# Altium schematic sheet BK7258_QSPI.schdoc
size 332 x 191 mm
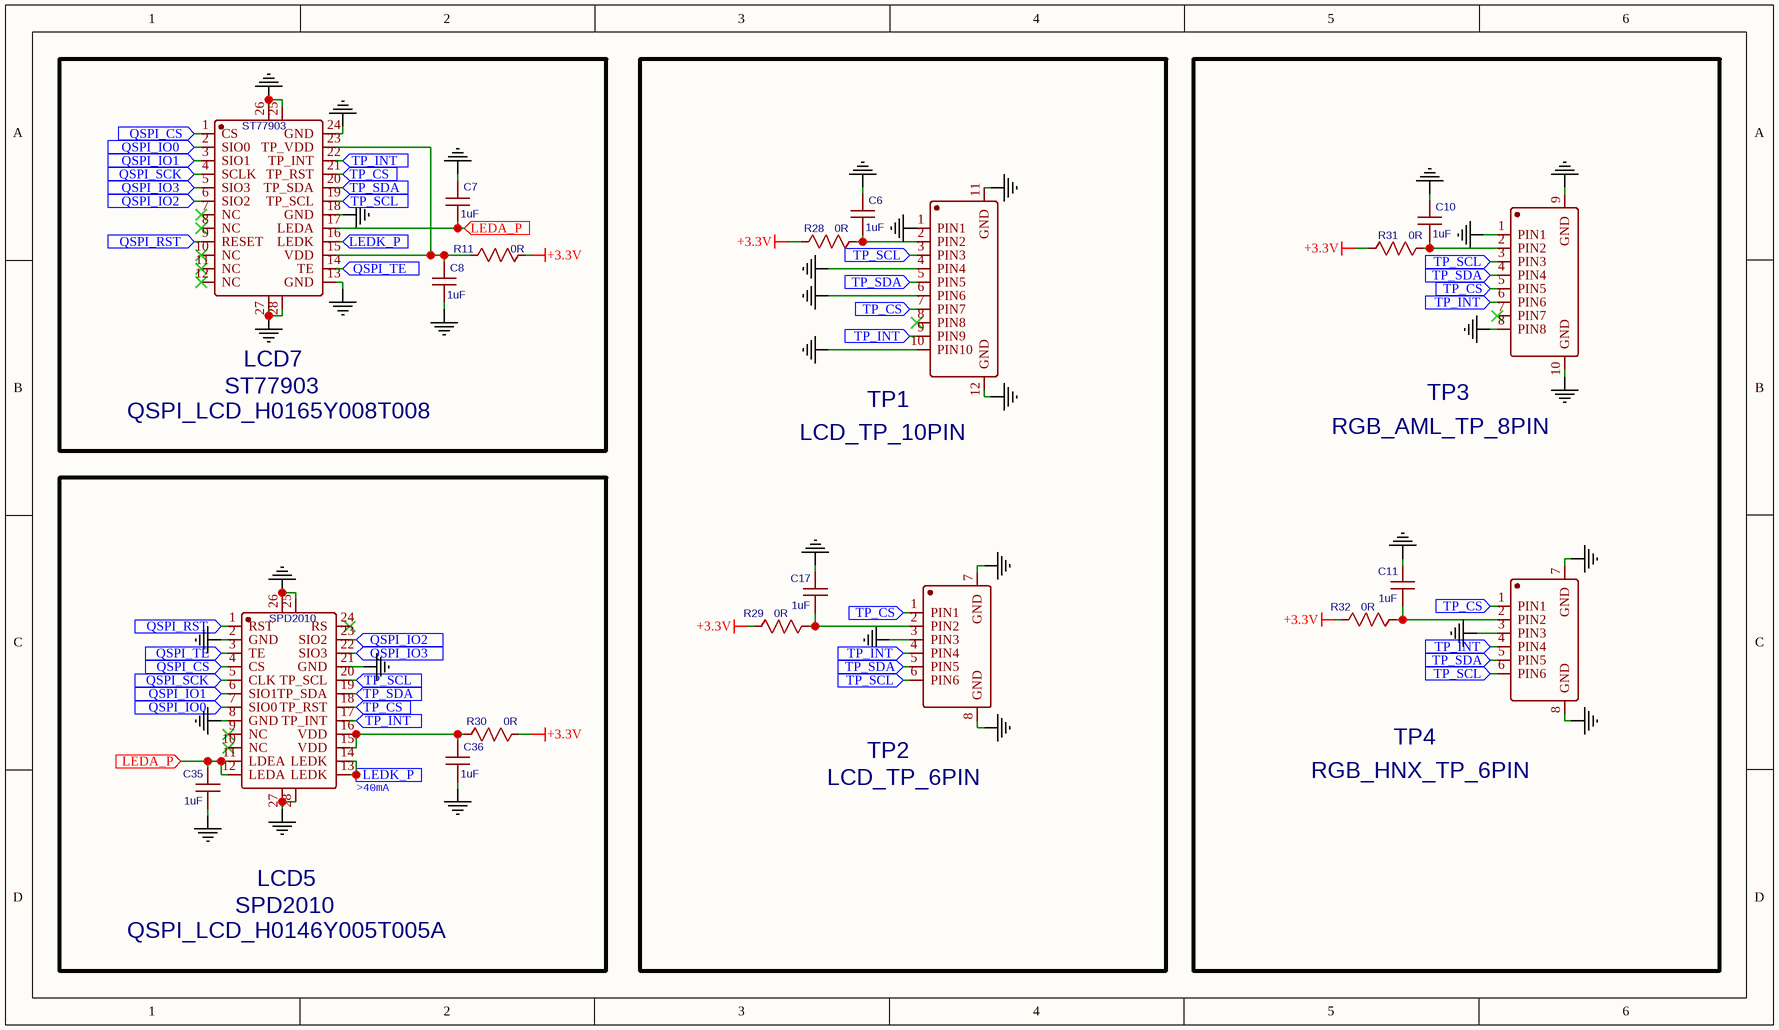
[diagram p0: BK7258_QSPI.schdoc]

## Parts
C6  1uF  [C0402]
C7  1uF  [C0402]
C8  1uF  [C0402]
C10  1uF  [C0402]
C11  1uF  [C0402]
C17  1uF  [C0402]
C35  1uF  [C0402]
C36  1uF  [C0402]
LCD5  SPD2010  [CONN-SMD_24P-P0.40_OK-14F024-04]
LCD7  ST77903  [CONN-SMD_24P-P0.40_OK-14F024-04]
R11  0R  [R0402]
R28  0R  [R0402]
R29  0R  [R0402]
R30  0R  [R0402]
R31  0R  [R0402]
R32  0R  [R0402]
TP1  LCD_TP_10PIN  [FPC-SMD_P0.5-10P_FGS-XJ-H2.0]
TP2  LCD_TP_6PIN  [CON6-FPC-AAAAA]
TP3  RGB_AML_TP_8PIN  [FPC-SMD_P0.50-8P_FGS-XJ-H2.0]
TP4  RGB_HNX_TP_6PIN  [CON6-FPC-HNX]

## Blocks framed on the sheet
QSPI_LCD_H0165Y008T008: C7 C8 LCD7 R11
QSPI_LCD_H0146Y005T005A: C35 C36 LCD5 R30

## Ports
LEDA_P (in), LEDK_P (in), QSPI_CS (in), QSPI_IO0 (in), QSPI_IO1 (in), QSPI_IO2 (in), QSPI_IO3 (in), QSPI_RST (in), QSPI_SCK (in), QSPI_TE (in), TP_CS (in), TP_INT (in), TP_SCL (in), TP_SDA (in)

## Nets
+3.3V: R11.2 R28.1 R29.1 R30.2 R31.1 R32.1
GGND: C6.1 C7.2 C8.2 C10.1 C11.1 C17.1 C35.2 C36.2 LCD5.2(GND) LCD5.8(GND) LCD5.21(GND) LCD5.25 LCD5.26 LCD5.27 LCD5.28 LCD7.13(GND) LCD7.18(GND) LCD7.24(GND) LCD7.25 LCD7.26 LCD7.27 LCD7.28 TP1.1(PIN1) TP1.4(PIN4) TP1.6(PIN6) TP1.10(PIN10) TP1.11(GND) TP1.12(GND) TP2.3(PIN3) TP2.7(GND) TP2.8(GND) TP3.1(PIN1) TP3.8(PIN8) TP3.9(GND) TP3.10(GND) TP4.3(PIN3) TP4.7(GND) TP4.8(GND)
LEDA_P: C7.1 C35.1 LCD5.11(LDEA) LCD5.12(LEDA) LCD7.17(LEDA) ; port LEDA_P
LEDK_P: LCD5.13(LEDK) LCD5.14(LEDK) LCD7.16(LEDK) ; port LEDK_P
QSPI_CS: LCD5.4(CS) LCD7.1(CS) ; port QSPI_CS
QSPI_IO0: LCD5.7(SIO0) LCD7.2(SIO0) ; port QSPI_IO0
QSPI_IO1: LCD5.6(SIO1) LCD7.3(SIO1) ; port QSPI_IO1
QSPI_IO2: LCD5.23(SIO2) LCD7.6(SIO2) ; port QSPI_IO2
QSPI_IO3: LCD5.22(SIO3) LCD7.5(SIO3) ; port QSPI_IO3
QSPI_RST: LCD5.1(RST) LCD7.9(RESET) ; port QSPI_RST
QSPI_SCK: LCD5.5(CLK) LCD7.4(SCLK) ; port QSPI_SCK
QSPI_TE: LCD5.3(TE) LCD7.14(TE) ; port QSPI_TE
TP_CS: LCD5.18(TP_RST) LCD7.21(TP_RST) TP1.7(PIN7) TP2.1(PIN1) TP3.5(PIN5) TP4.1(PIN1) ; port TP_CS
TP_INT: LCD5.17(TP_INT) LCD7.22(TP_INT) TP1.9(PIN9) TP2.4(PIN4) TP3.6(PIN6) TP4.4(PIN4) ; port TP_INT
TP_SCL: LCD5.20(TP_SCL) LCD7.19(TP_SCL) TP1.3(PIN3) TP2.6(PIN6) TP3.3(PIN3) TP4.6(PIN6) ; port TP_SCL
TP_SDA: LCD5.19(TP_SDA) LCD7.20(TP_SDA) TP1.5(PIN5) TP2.5(PIN5) TP3.4(PIN4) TP4.5(PIN5) ; port TP_SDA
NetC6_2: C6.2 R28.2 TP1.2(PIN2)
NetC8_1: C8.1 LCD7.15(VDD) LCD7.23(TP_VDD) R11.1
NetC10_2: C10.2 R31.2 TP3.2(PIN2)
NetC11_2: C11.2 R32.2 TP4.2(PIN2)
NetC17_2: C17.2 R29.2 TP2.2(PIN2)
NetC36_1: C36.1 LCD5.15(VDD) LCD5.16(VDD) R30.1

Not connected (* = marked no-connect by the designer): LCD5 9(NC)* 10(NC)* 24(RS)*; LCD7 7(NC)* 8(NC)* 10(NC)* 11(NC)* 12(NC)*; TP1 8(PIN8)*; TP3 7(PIN7)*

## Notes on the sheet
- (near LCD5) >40mA

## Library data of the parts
C6-C8 C10 C11 C17 C35 C36 = 1uF: Manufacturer Part: CL05A105KO5NNNC; BOM_Manufacturer: SAMSUNG(三星)
LCD5 = SPD2010: BOM_Manufacturer: HRS(广濑); BOM_Manufacturer Part: BM20B(0.8)-24DS-0.4V(51); Contributor: qunshan.xu
LCD7 = ST77903: BOM_Manufacturer: HRS(广濑); BOM_Manufacturer Part: BM20B(0.8)-24DS-0.4V(51); Contributor: qunshan.xu
R11 R28-R32 = 0R: Manufacturer Part: 0402WGF0000TCE; BOM_Manufacturer: UNI-ROYAL(厚声); nameAlias: Value(Ω); Contributor: LCEDA_Lib
TP1 = LCD_TP_10PIN: BOM_Manufacturer: JS（钜硕）; BOM_Manufacturer Part: AFC01-S10FCA-00; Contributor: jian.shi1
TP2 = LCD_TP_6PIN: BOM_Manufacturer: JS(钜硕电子); BOM_Manufacturer Part: AFC01-S06FCA-00; Contributor: jian.shi1
TP3 = RGB_AML_TP_8PIN: BOM_Manufacturer: JS(钜硕电子); BOM_Manufacturer Part: AFC01-S08FCA-00; Contributor: jian.shi1
TP4 = RGB_HNX_TP_6PIN: BOM_Manufacturer: JS(钜硕电子); BOM_Manufacturer Part: AFC01-S06FCA-00; Contributor: jian.shi1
